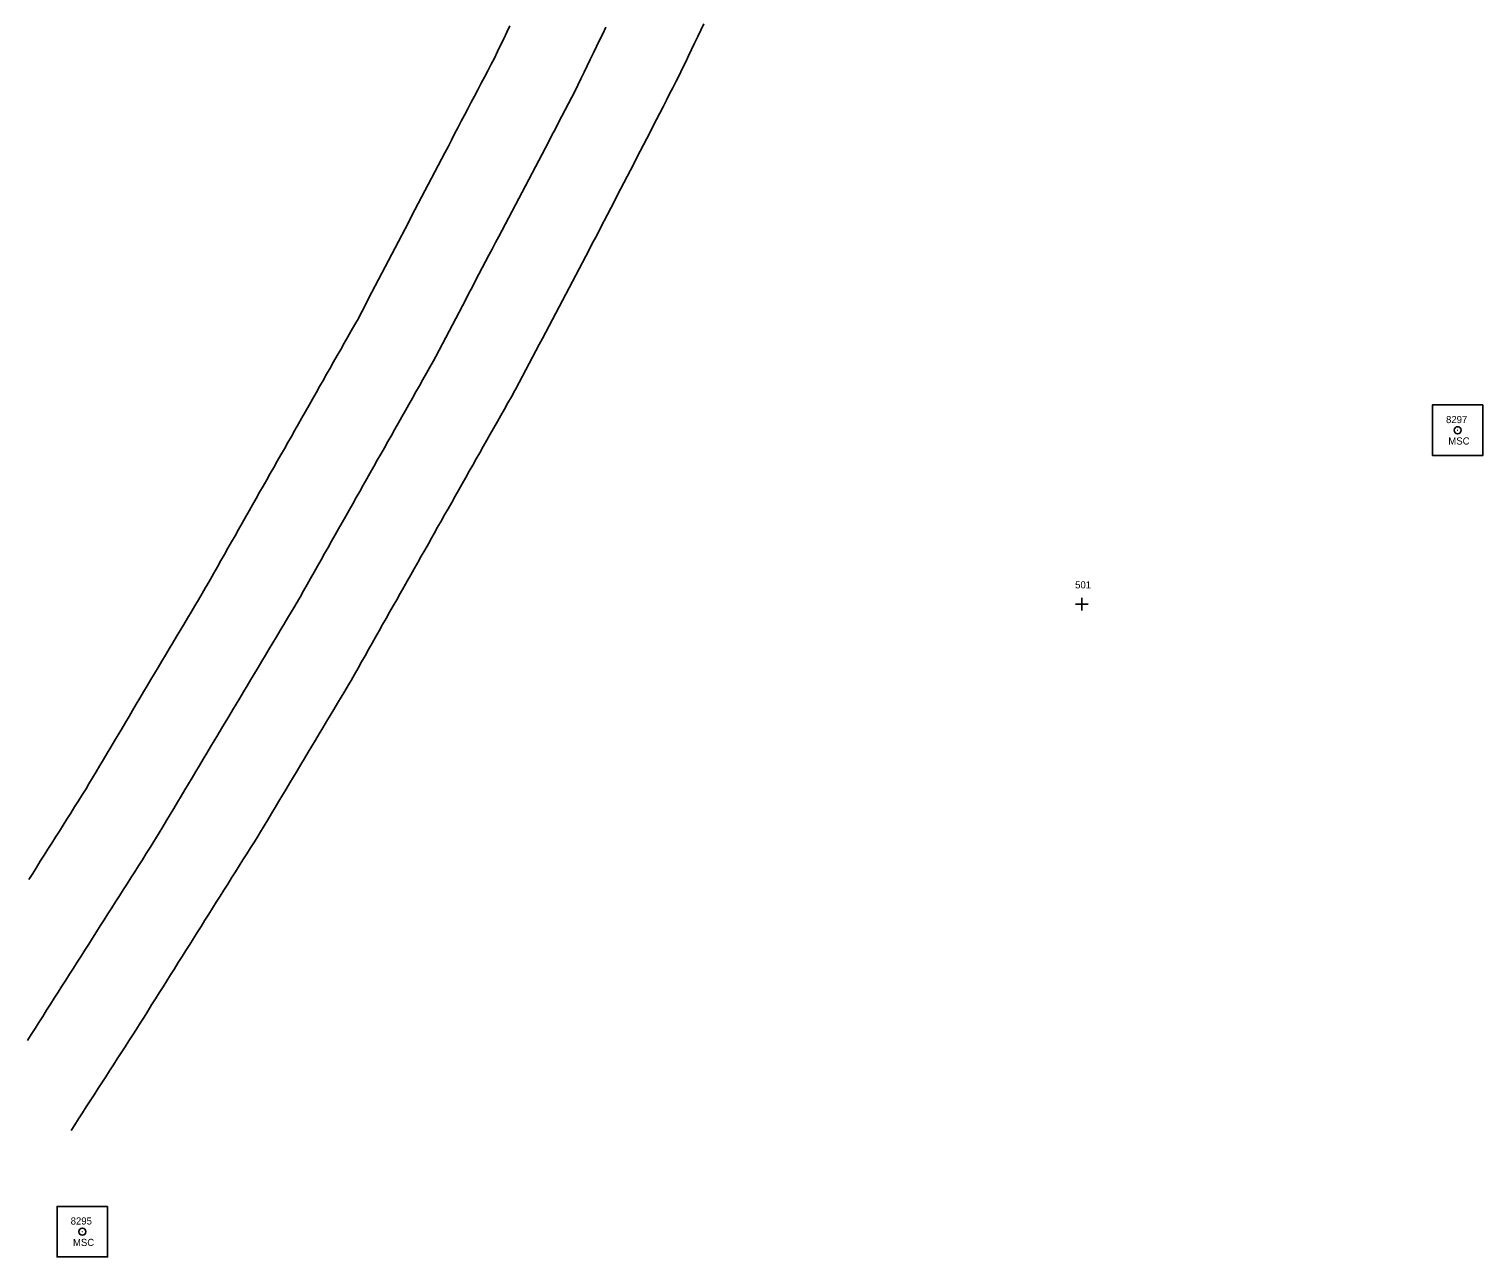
# Model space of a CAD drawing. Extents: x 205929 to 2357175, y -1785700 to 846739.
# Drawn here: x 2023134 to 2023337.5, y 806834.9 to 807006.8 of the extents above; entities that cross this region are included whole.
import ezdxf

# ---------------------------------------------------------------- set-up
doc = ezdxf.new("R2010")
doc.units = 0
for name, color, linetype in [('Default', 7, 'Continuous'), ('RD_HC_Survey', 7, 'Continuous'), ('RD_HC_txCode', 7, 'Continuous'), ('RD_Sketch1', 7, 'Continuous'), ('RD_SMD_Locator', 7, 'Continuous')]:
    doc.layers.add(name, color=color, linetype=linetype)

msp = doc.modelspace()

# ---------------------------------------------------------------- linework, layer by layer
at = {"layer": 'Default'}
for p, q in [((2023281.37, 806927.18), (2023281.37, 806925.43)), ((2023282.25, 806926.31), (2023280.5, 806926.31))]:
    msp.add_line(p, q, dxfattribs=at)
at = {"layer": 'RD_HC_Survey'}
for points in [[(2023337.54, 806954.19), (2023330.46, 806954.19), (2023330.46, 806947.12), (2023337.54, 806947.12)], [(2023144.97, 806841.97), (2023137.9, 806841.97), (2023137.9, 806834.9), (2023144.97, 806834.9)]]:
    msp.add_lwpolyline(points, close=True, dxfattribs=at)
for centre in [(2023334, 806950.65), (2023141.43, 806838.43)]:
    msp.add_circle(centre, 0.5, dxfattribs=at)
at = {"layer": 'RD_Sketch1'}
for points in [[(2023214.74, 807007.07), (2023214.3, 807006.17), (2023213.86, 807005.27), (2023213.43, 807004.37), (2023212.99, 807003.48), (2023212.55, 807002.58), (2023212.12, 807001.68), (2023211.68, 807000.78), (2023211.24, 806999.88), (2023210.81, 806998.98), (2023210.37, 806998.08), (2023209.98, 806997.28), (2023209.52, 806996.39), (2023209.05, 806995.51), (2023208.59, 806994.62), (2023208.12, 806993.74), (2023207.66, 806992.85), (2023207.19, 806991.97), (2023206.73, 806991.08), (2023206.26, 806990.2), (2023205.8, 806989.31), (2023205.33, 806988.43), (2023204.87, 806987.54), (2023204.4, 806986.66), (2023203.94, 806985.77), (2023203.47, 806984.89), (2023203.01, 806984), (2023202.54, 806983.11), (2023202.08, 806982.23), (2023201.61, 806981.34), (2023201.15, 806980.46), (2023200.68, 806979.57), (2023200.22, 806978.69), (2023199.75, 806977.8), (2023199.29, 806976.92), (2023198.82, 806976.03), (2023198.36, 806975.15), (2023197.89, 806974.26), (2023197.43, 806973.38), (2023196.96, 806972.49), (2023196.5, 806971.61), (2023196.04, 806970.72), (2023195.57, 806969.84), (2023195.11, 806968.95), (2023194.64, 806968.06), (2023194.18, 806967.18), (2023193.71, 806966.29), (2023193.25, 806965.41), (2023192.78, 806964.52), (2023192.32, 806963.64), (2023191.85, 806962.75), (2023191.39, 806961.87), (2023190.92, 806960.98), (2023190.6, 806960.37), (2023190.11, 806959.5), (2023189.62, 806958.63), (2023189.13, 806957.76), (2023188.64, 806956.89), (2023188.14, 806956.02), (2023187.65, 806955.15), (2023187.16, 806954.28), (2023186.67, 806953.41), (2023186.18, 806952.54), (2023185.68, 806951.67), (2023185.19, 806950.8), (2023184.7, 806949.93), (2023184.21, 806949.06), (2023183.72, 806948.19), (2023183.23, 806947.31), (2023182.73, 806946.44), (2023182.24, 806945.57), (2023181.75, 806944.7), (2023181.26, 806943.83), (2023180.77, 806942.96), (2023180.27, 806942.09), (2023179.78, 806941.22), (2023179.29, 806940.35), (2023178.8, 806939.48), (2023178.31, 806938.61), (2023177.82, 806937.74), (2023177.32, 806936.87), (2023176.83, 806936), (2023176.34, 806935.13), (2023175.85, 806934.25), (2023175.36, 806933.38), (2023174.86, 806932.51), (2023174.37, 806931.64), (2023173.88, 806930.77), (2023173.39, 806929.9), (2023172.9, 806929.03), (2023172.41, 806928.16), (2023171.91, 806927.29), (2023171.69, 806926.89), (2023171.18, 806926.03), (2023170.66, 806925.18), (2023170.15, 806924.32), (2023169.64, 806923.46), (2023169.12, 806922.6), (2023168.61, 806921.74), (2023168.1, 806920.88), (2023167.58, 806920.03), (2023167.07, 806919.17), (2023166.56, 806918.31), (2023166.04, 806917.45), (2023165.53, 806916.59), (2023165.02, 806915.74), (2023164.51, 806914.88), (2023163.99, 806914.02), (2023163.48, 806913.16), (2023162.97, 806912.3), (2023162.45, 806911.44), (2023161.94, 806910.59), (2023161.43, 806909.73), (2023160.91, 806908.87), (2023160.4, 806908.01), (2023159.89, 806907.15), (2023159.37, 806906.3), (2023158.86, 806905.44), (2023158.35, 806904.58), (2023157.83, 806903.72), (2023157.32, 806902.86), (2023156.81, 806902), (2023156.29, 806901.15), (2023155.78, 806900.29), (2023155.27, 806899.43), (2023154.75, 806898.57), (2023154.24, 806897.71), (2023153.73, 806896.86), (2023153.21, 806896), (2023152.7, 806895.14), (2023152.19, 806894.28), (2023151.68, 806893.42), (2023151.45, 806893.05), (2023150.92, 806892.21), (2023150.38, 806891.37), (2023149.84, 806890.52), (2023149.31, 806889.68), (2023148.77, 806888.83), (2023148.24, 806887.99), (2023147.7, 806887.15), (2023147.16, 806886.3), (2023146.63, 806885.46), (2023146.09, 806884.62), (2023145.55, 806883.77), (2023145.02, 806882.93), (2023144.48, 806882.08), (2023143.94, 806881.24), (2023143.41, 806880.4), (2023142.87, 806879.55), (2023142.33, 806878.71), (2023141.8, 806877.86), (2023141.26, 806877.02), (2023140.72, 806876.18), (2023140.19, 806875.33), (2023139.65, 806874.49), (2023139.11, 806873.65), (2023138.58, 806872.8), (2023138.04, 806871.96), (2023137.5, 806871.11), (2023136.97, 806870.27), (2023136.43, 806869.43), (2023135.89, 806868.58), (2023135.36, 806867.74), (2023134.82, 806866.89), (2023134.28, 806866.05), (2023133.75, 806865.21)], [(2023201.31, 807007.27), (2023200.87, 807006.37), (2023200.43, 807005.47), (2023199.99, 807004.57), (2023199.56, 807003.67), (2023199.12, 807002.77), (2023198.66, 807001.89), (2023198.19, 807001), (2023197.73, 807000.11), (2023197.27, 806999.23), (2023196.8, 806998.34), (2023196.34, 806997.45), (2023195.88, 806996.57), (2023195.42, 806995.68), (2023194.95, 806994.79), (2023194.49, 806993.91), (2023194.03, 806993.02), (2023193.56, 806992.14), (2023193.1, 806991.25), (2023192.64, 806990.36), (2023192.17, 806989.48), (2023191.71, 806988.59), (2023191.25, 806987.7), (2023190.78, 806986.82), (2023190.32, 806985.93), (2023189.86, 806985.04), (2023189.4, 806984.16), (2023188.93, 806983.27), (2023188.47, 806982.39), (2023188.01, 806981.5), (2023187.54, 806980.61), (2023187.08, 806979.73), (2023186.62, 806978.84), (2023186.15, 806977.95), (2023185.69, 806977.07), (2023185.23, 806976.18), (2023184.77, 806975.3), (2023184.3, 806974.41), (2023183.84, 806973.52), (2023183.38, 806972.64), (2023182.91, 806971.75), (2023182.45, 806970.86), (2023181.99, 806969.98), (2023181.52, 806969.09), (2023181.06, 806968.2), (2023180.6, 806967.32), (2023180.14, 806966.43), (2023180.08, 806966.32), (2023179.58, 806965.45), (2023179.09, 806964.58), (2023178.6, 806963.71), (2023178.1, 806962.84), (2023177.61, 806961.97), (2023177.12, 806961.1), (2023176.62, 806960.23), (2023176.13, 806959.36), (2023175.64, 806958.49), (2023175.14, 806957.63), (2023174.65, 806956.76), (2023174.16, 806955.89), (2023173.66, 806955.02), (2023173.17, 806954.15), (2023172.68, 806953.28), (2023172.18, 806952.41), (2023171.69, 806951.54), (2023171.2, 806950.67), (2023170.7, 806949.8), (2023170.21, 806948.93), (2023169.72, 806948.06), (2023169.22, 806947.19), (2023168.73, 806946.32), (2023168.24, 806945.45), (2023167.74, 806944.58), (2023167.25, 806943.71), (2023166.76, 806942.84), (2023166.26, 806941.97), (2023165.77, 806941.1), (2023165.28, 806940.23), (2023164.78, 806939.36), (2023164.29, 806938.49), (2023163.8, 806937.62), (2023163.3, 806936.75), (2023162.81, 806935.88), (2023162.32, 806935.01), (2023161.82, 806934.14), (2023161.33, 806933.27), (2023160.84, 806932.4), (2023160.34, 806931.53), (2023159.85, 806930.66), (2023159.36, 806929.79), (2023158.86, 806928.92), (2023158.7, 806928.63), (2023158.19, 806927.77), (2023157.68, 806926.91), (2023157.17, 806926.05), (2023156.65, 806925.19), (2023156.14, 806924.33), (2023155.63, 806923.47), (2023155.12, 806922.61), (2023154.61, 806921.75), (2023154.1, 806920.89), (2023153.59, 806920.03), (2023153.08, 806919.17), (2023152.57, 806918.31), (2023152.06, 806917.45), (2023151.55, 806916.59), (2023151.04, 806915.73), (2023150.53, 806914.87), (2023150.01, 806914.01), (2023149.5, 806913.15), (2023148.99, 806912.29), (2023148.48, 806911.43), (2023147.97, 806910.57), (2023147.46, 806909.71), (2023146.95, 806908.85), (2023146.44, 806908), (2023145.93, 806907.14), (2023145.42, 806906.28), (2023144.91, 806905.42), (2023144.4, 806904.56), (2023143.89, 806903.7), (2023143.37, 806902.84), (2023142.86, 806901.98), (2023142.35, 806901.12), (2023141.95, 806900.44), (2023141.42, 806899.59), (2023140.88, 806898.75), (2023140.35, 806897.9), (2023139.82, 806897.05), (2023139.28, 806896.21), (2023138.75, 806895.36), (2023138.22, 806894.52), (2023137.68, 806893.67), (2023137.15, 806892.83), (2023136.62, 806891.98), (2023136.08, 806891.13), (2023135.55, 806890.29), (2023135.02, 806889.44), (2023134.48, 806888.6), (2023133.95, 806887.75)], [(2023228.44, 807007.58), (2023228.02, 807006.67), (2023227.59, 807005.77), (2023227.16, 807004.87), (2023226.73, 807003.96), (2023226.3, 807003.06), (2023225.87, 807002.16), (2023225.44, 807001.25), (2023225.04, 807000.4), (2023224.58, 806999.51), (2023224.12, 806998.62), (2023223.66, 806997.74), (2023223.21, 806996.85), (2023222.75, 806995.96), (2023222.29, 806995.07), (2023221.83, 806994.18), (2023221.38, 806993.29), (2023220.92, 806992.4), (2023220.46, 806991.51), (2023220, 806990.62), (2023219.54, 806989.73), (2023219.09, 806988.85), (2023218.63, 806987.96), (2023218.17, 806987.07), (2023217.71, 806986.18), (2023217.25, 806985.29), (2023216.8, 806984.4), (2023216.34, 806983.51), (2023215.88, 806982.62), (2023215.42, 806981.73), (2023214.96, 806980.85), (2023214.51, 806979.96), (2023214.24, 806979.44), (2023213.78, 806978.56), (2023213.31, 806977.67), (2023212.84, 806976.79), (2023212.38, 806975.9), (2023211.91, 806975.02), (2023211.44, 806974.13), (2023210.98, 806973.25), (2023210.51, 806972.37), (2023210.04, 806971.48), (2023209.58, 806970.6), (2023209.11, 806969.71), (2023208.64, 806968.83), (2023208.18, 806967.94), (2023207.71, 806967.06), (2023207.25, 806966.17), (2023206.78, 806965.29), (2023206.31, 806964.4), (2023205.85, 806963.52), (2023205.38, 806962.64), (2023204.91, 806961.75), (2023204.45, 806960.87), (2023203.98, 806959.98), (2023203.51, 806959.1), (2023203.05, 806958.21), (2023202.58, 806957.33), (2023202.11, 806956.44), (2023202, 806956.22), (2023201.5, 806955.35), (2023201.01, 806954.48), (2023200.52, 806953.61), (2023200.03, 806952.74), (2023199.54, 806951.86), (2023199.05, 806950.99), (2023198.55, 806950.12), (2023198.06, 806949.25), (2023197.57, 806948.38), (2023197.08, 806947.51), (2023196.59, 806946.64), (2023196.1, 806945.77), (2023195.6, 806944.9), (2023195.11, 806944.03), (2023194.62, 806943.16), (2023194.13, 806942.29), (2023193.64, 806941.41), (2023193.15, 806940.54), (2023192.66, 806939.67), (2023192.16, 806938.8), (2023191.67, 806937.93), (2023191.18, 806937.06), (2023190.69, 806936.19), (2023190.37, 806935.62), (2023189.88, 806934.75), (2023189.38, 806933.88), (2023188.89, 806933.01), (2023188.4, 806932.14), (2023187.91, 806931.27), (2023187.41, 806930.4), (2023186.92, 806929.53), (2023186.43, 806928.66), (2023185.94, 806927.79), (2023185.45, 806926.92), (2023184.95, 806926.05), (2023184.46, 806925.18), (2023183.97, 806924.31), (2023183.48, 806923.43), (2023182.99, 806922.56), (2023182.49, 806921.69), (2023182, 806920.82), (2023181.51, 806919.95), (2023181.02, 806919.08), (2023180.52, 806918.21), (2023180.03, 806917.34), (2023179.54, 806916.47), (2023179.05, 806915.6), (2023178.7, 806914.99), (2023178.19, 806914.13), (2023177.68, 806913.28), (2023177.16, 806912.42), (2023176.65, 806911.56), (2023176.13, 806910.7), (2023175.62, 806909.85), (2023175.11, 806908.99), (2023174.59, 806908.13), (2023174.08, 806907.27), (2023173.56, 806906.41), (2023173.05, 806905.56), (2023172.54, 806904.7), (2023172.02, 806903.84), (2023171.51, 806902.98), (2023170.99, 806902.13), (2023170.48, 806901.27), (2023169.96, 806900.41), (2023169.45, 806899.55), (2023168.94, 806898.7), (2023168.42, 806897.84), (2023167.91, 806896.98), (2023167.39, 806896.12), (2023166.88, 806895.26), (2023166.37, 806894.41), (2023166.05, 806893.88), (2023165.52, 806893.03), (2023164.99, 806892.19), (2023164.45, 806891.34), (2023163.92, 806890.5), (2023163.39, 806889.65), (2023162.86, 806888.8), (2023162.32, 806887.96), (2023161.79, 806887.11), (2023161.26, 806886.26), (2023160.73, 806885.42), (2023160.19, 806884.57), (2023159.66, 806883.72), (2023159.13, 806882.88), (2023158.6, 806882.03), (2023158.06, 806881.18), (2023157.53, 806880.34), (2023157, 806879.49), (2023156.47, 806878.65), (2023155.93, 806877.8), (2023155.4, 806876.95), (2023154.87, 806876.11), (2023154.34, 806875.26), (2023153.8, 806874.41), (2023153.27, 806873.57), (2023152.74, 806872.72), (2023152.21, 806871.87), (2023151.67, 806871.03), (2023151.14, 806870.18), (2023150.61, 806869.33), (2023150.08, 806868.49), (2023149.54, 806867.64), (2023149.01, 806866.8), (2023148.5, 806865.98), (2023147.96, 806865.14), (2023147.42, 806864.31), (2023146.87, 806863.47), (2023146.33, 806862.63), (2023145.79, 806861.79), (2023145.24, 806860.95), (2023144.7, 806860.11), (2023144.16, 806859.27), (2023143.61, 806858.43), (2023143.07, 806857.59), (2023142.53, 806856.75), (2023141.98, 806855.91), (2023141.44, 806855.07), (2023140.9, 806854.23), (2023140.36, 806853.39), (2023139.85, 806852.61)]]:
    msp.add_lwpolyline(points, dxfattribs=at)
at = {"layer": 'RD_SMD_Locator'}
for centre in [(2023334, 806950.65), (2023141.43, 806838.43)]:
    msp.add_circle(centre, 0.001, dxfattribs=at)

# ---------------------------------------------------------------- texts
at = {"layer": 'Default'}
msp.add_text('501', height=1, dxfattribs=at).set_placement((2023280.44, 806928.51))
at = {"layer": 'RD_HC_txCode'}
for s, p in [('8297', (2023332.37, 806951.65)), ('MSC', (2023332.69, 806948.65)), ('8295', (2023139.8, 806839.43)), ('MSC', (2023140.12, 806836.43))]:
    msp.add_text(s, height=1, dxfattribs=at).set_placement(p)

doc.saveas('drawing.dxf')
